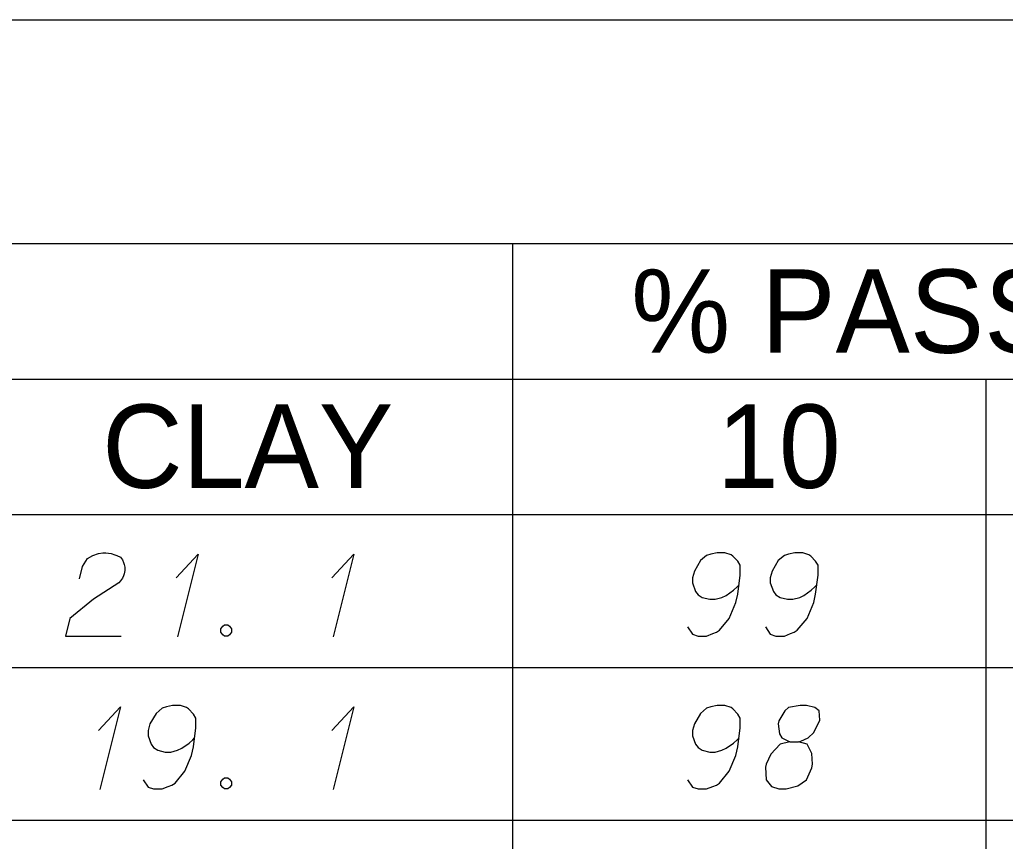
# Model space of a CAD drawing. Extents: x 2074207 to 2076812, y 516372 to 523312.
# Drawn here: x 2076621.8 to 2076678.5, y 517239.3 to 517286.6 of the extents above; entities that cross this region are included whole.
import ezdxf

# ---------------------------------------------------------------- set-up
doc = ezdxf.new("R2010")
doc.units = 0
for name, color, linetype in [('Prop DirtTable_ Soil Test Results - Outline (Major)', 7, 'Continuous'), ('Prop DirtTable_ Soil Test Results - Outline (Minor)', 7, 'Continuous'), ('Prop DirtTable_ Soil Test Results - Tx (Header - Small)', 7, 'Continuous'), ('Prop DirtTable_ Soil Test Results - Tx (Sample Data)', 7, 'Continuous')]:
    doc.layers.add(name, color=color, linetype=linetype)

msp = doc.modelspace()

# ---------------------------------------------------------------- linework, layer by layer
at = {"layer": 'Prop DirtTable_ Soil Test Results - Outline (Major)'}
for p, q in [((2076260.609, 517286.581), (2076811.903, 517286.581)), ((2076260.609, 517258.096), (2076811.903, 517258.096)), ((2076260.609, 517258.096), (2076811.903, 517258.096))]:
    msp.add_line(p, q, dxfattribs=at)
at = {"layer": 'Prop DirtTable_ Soil Test Results - Outline (Minor)'}
for p, q in [((2076260.609, 517273.696), (2076811.903, 517273.696)), ((2076650.154, 517273.696), (2076650.154, 517249.296)), ((2076526.074, 517265.896), (2076731.93, 517265.896)), ((2076677.413, 517265.896), (2076677.413, 517249.296)), ((2076260.609, 517249.296), (2076811.903, 517249.296)), ((2076260.609, 517249.296), (2076811.903, 517249.296)), ((2076650.154, 517249.296), (2076650.154, 517240.496)), ((2076677.413, 517249.296), (2076677.413, 517240.496)), ((2076260.609, 517240.496), (2076811.903, 517240.496)), ((2076260.609, 517240.496), (2076811.903, 517240.496)), ((2076650.154, 517240.496), (2076650.154, 517231.696)), ((2076677.413, 517240.496), (2076677.413, 517231.696))]:
    msp.add_line(p, q, dxfattribs=at)
at = {"layer": 'Prop DirtTable_ Soil Test Results - Tx (Sample Data)'}
for points in [[(2076625.207, 517254.386), (2076625.383, 517255.104), (2076625.666, 517255.558), (2076625.983, 517255.747), (2076626.3, 517255.86), (2076626.547, 517255.898), (2076626.724, 517255.898), (2076627.041, 517255.86), (2076627.253, 517255.785), (2076627.359, 517255.747), (2076627.57, 517255.633), (2076627.676, 517255.482), (2076627.747, 517255.331), (2076627.782, 517255.218), (2076627.817, 517255.067), (2076627.817, 517254.878), (2076627.782, 517254.689), (2076627.747, 517254.575), (2076627.676, 517254.424), (2076627.57, 517254.273), (2076627.465, 517254.159), (2076626.018, 517253.215), (2076624.643, 517252.118), (2076624.396, 517251.098), (2076627.606, 517251.098)], [(2076630.78, 517254.462), (2076632.05, 517255.822), (2076630.851, 517251.06)], [(2076639.74, 517254.462), (2076641.01, 517255.822), (2076639.811, 517251.06)], [(2076660.236, 517251.627), (2076660.518, 517251.211), (2076660.835, 517251.098), (2076661.329, 517251.098), (2076661.682, 517251.249), (2076661.894, 517251.325), (2076662.07, 517251.438), (2076662.634, 517252.118), (2076663.022, 517253.026), (2076663.128, 517253.517), (2076663.269, 517254.613), (2076663.269, 517255.18), (2076663.128, 517255.407), (2076662.846, 517255.709), (2076662.74, 517255.785), (2076662.387, 517255.898), (2076661.929, 517255.898), (2076661.576, 517255.822), (2076661.329, 517255.747), (2076660.976, 517255.444), (2076660.624, 517254.84), (2076660.518, 517254.462), (2076660.518, 517254.159), (2076660.694, 517253.668), (2076660.835, 517253.479), (2076661.082, 517253.328), (2076661.506, 517253.215), (2076661.823, 517253.215), (2076662.211, 517253.328), (2076662.458, 517253.441), (2076662.881, 517253.744), (2076663.093, 517253.933), (2076663.199, 517254.046)], [(2076664.716, 517251.627), (2076664.998, 517251.211), (2076665.315, 517251.098), (2076665.809, 517251.098), (2076666.162, 517251.249), (2076666.374, 517251.325), (2076666.55, 517251.438), (2076667.114, 517252.118), (2076667.502, 517253.026), (2076667.608, 517253.517), (2076667.749, 517254.613), (2076667.749, 517255.18), (2076667.608, 517255.407), (2076667.326, 517255.709), (2076667.22, 517255.785), (2076666.867, 517255.898), (2076666.409, 517255.898), (2076666.056, 517255.822), (2076665.809, 517255.747), (2076665.456, 517255.444), (2076665.104, 517254.84), (2076664.998, 517254.462), (2076664.998, 517254.159), (2076665.174, 517253.668), (2076665.315, 517253.479), (2076665.562, 517253.328), (2076665.986, 517253.215), (2076666.303, 517253.215), (2076666.691, 517253.328), (2076666.938, 517253.441), (2076667.361, 517253.744), (2076667.573, 517253.933), (2076667.679, 517254.046)], [(2076633.567, 517251.741), (2076633.744, 517251.741), (2076633.849, 517251.665), (2076633.955, 517251.514), (2076633.955, 517251.325), (2076633.849, 517251.174), (2076633.744, 517251.098), (2076633.567, 517251.098), (2076633.461, 517251.174), (2076633.356, 517251.325), (2076633.356, 517251.514), (2076633.461, 517251.665), (2076633.567, 517251.741)], [(2076626.3, 517245.662), (2076627.57, 517247.022), (2076626.371, 517242.26)], [(2076628.876, 517242.827), (2076629.158, 517242.411), (2076629.475, 517242.298), (2076629.969, 517242.298), (2076630.322, 517242.449), (2076630.534, 517242.525), (2076630.71, 517242.638), (2076631.274, 517243.318), (2076631.662, 517244.226), (2076631.768, 517244.717), (2076631.909, 517245.813), (2076631.909, 517246.38), (2076631.768, 517246.607), (2076631.486, 517246.909), (2076631.38, 517246.985), (2076631.027, 517247.098), (2076630.569, 517247.098), (2076630.216, 517247.022), (2076629.969, 517246.947), (2076629.616, 517246.644), (2076629.264, 517246.04), (2076629.158, 517245.662), (2076629.158, 517245.359), (2076629.334, 517244.868), (2076629.475, 517244.679), (2076629.722, 517244.528), (2076630.146, 517244.415), (2076630.463, 517244.415), (2076630.851, 517244.528), (2076631.098, 517244.641), (2076631.521, 517244.944), (2076631.733, 517245.133), (2076631.839, 517245.246)], [(2076639.74, 517245.662), (2076641.01, 517247.022), (2076639.811, 517242.26)], [(2076660.236, 517242.827), (2076660.518, 517242.411), (2076660.835, 517242.298), (2076661.329, 517242.298), (2076661.682, 517242.449), (2076661.894, 517242.525), (2076662.07, 517242.638), (2076662.634, 517243.318), (2076663.022, 517244.226), (2076663.128, 517244.717), (2076663.269, 517245.813), (2076663.269, 517246.38), (2076663.128, 517246.607), (2076662.846, 517246.909), (2076662.74, 517246.985), (2076662.387, 517247.098), (2076661.929, 517247.098), (2076661.576, 517247.022), (2076661.329, 517246.947), (2076660.976, 517246.644), (2076660.624, 517246.04), (2076660.518, 517245.662), (2076660.518, 517245.359), (2076660.694, 517244.868), (2076660.835, 517244.679), (2076661.082, 517244.528), (2076661.506, 517244.415), (2076661.823, 517244.415), (2076662.211, 517244.528), (2076662.458, 517244.641), (2076662.881, 517244.944), (2076663.093, 517245.133), (2076663.199, 517245.246)], [(2076666.127, 517245.019), (2076666.62, 517245.019), (2076666.762, 517245.057), (2076667.185, 517245.246), (2076667.502, 517245.548), (2076667.855, 517246.267), (2076667.82, 517246.796), (2076667.573, 517246.985), (2076667.079, 517247.098), (2076666.726, 517247.098), (2076666.056, 517246.985), (2076665.844, 517246.796), (2076665.492, 517246.229), (2076665.456, 517246.04), (2076665.527, 517245.473), (2076665.668, 517245.246), (2076666.127, 517245.019), (2076665.562, 517244.868), (2076665.033, 517244.301), (2076664.751, 517243.734), (2076664.716, 517243.545), (2076664.751, 517242.827), (2076665.068, 517242.449), (2076665.492, 517242.298), (2076665.915, 517242.298), (2076666.585, 517242.487), (2076667.079, 517242.827), (2076667.397, 517243.507), (2076667.432, 517243.734), (2076667.397, 517244.339), (2076667.114, 517244.868), (2076666.62, 517245.019)], [(2076633.567, 517242.941), (2076633.744, 517242.941), (2076633.849, 517242.865), (2076633.955, 517242.714), (2076633.955, 517242.525), (2076633.849, 517242.374), (2076633.744, 517242.298), (2076633.567, 517242.298), (2076633.461, 517242.374), (2076633.356, 517242.525), (2076633.356, 517242.714), (2076633.461, 517242.865), (2076633.567, 517242.941)]]:
    msp.add_lwpolyline(points, dxfattribs=at)

# ---------------------------------------------------------------- texts
at = {"layer": 'Prop DirtTable_ Soil Test Results - Tx (Header - Small)'}
for s, height, p in [('% PASSING (SIEVES)', 4.79998, (2076656.984, 517267.406)), ('CLAY', 4.8, (2076626.513, 517259.631)), ('10', 4.8, (2076661.92, 517259.631))]:
    msp.add_text(s, height=height, dxfattribs=at).set_placement(p)

doc.saveas('drawing.dxf')
